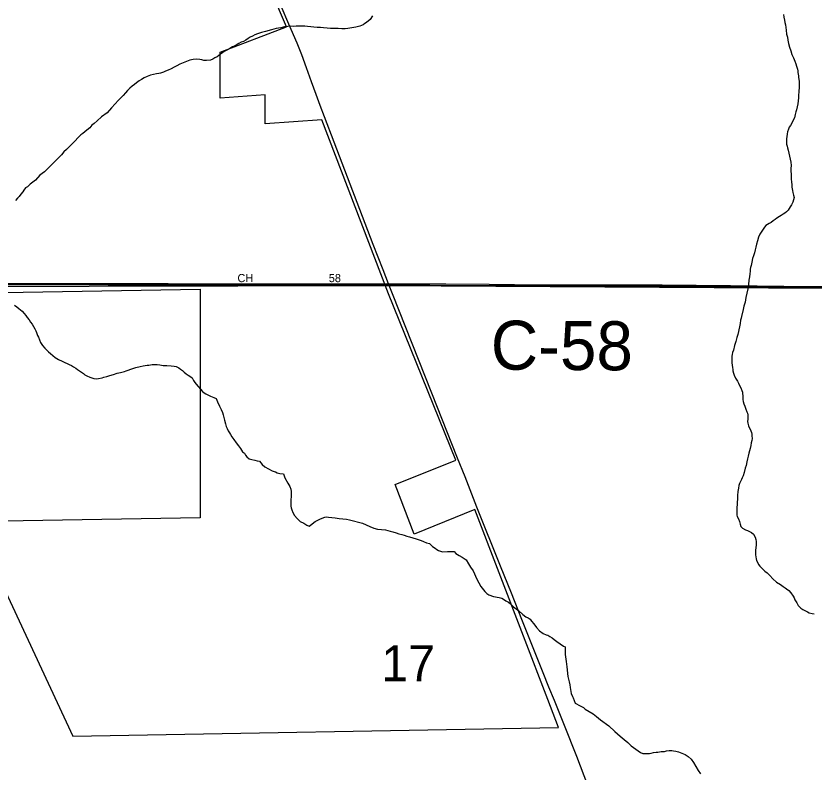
# Model space of a CAD drawing. Extents: x -17 to 88, y -5 to 22.
# Drawn here: x 3.752 to 4.677, y 17.592 to 18.469 of the extents above; entities that cross this region are included whole.
import ezdxf

# ---------------------------------------------------------------- set-up
doc = ezdxf.new("R2010")
doc.units = 0
for name, color, linetype in [('GM_X_City_Street', 7, 'Continuous'), ('GM_X_City_Street_Text', 7, 'Continuous'), ('GM_X_Corporation', 7, 'Continuous'), ('GM_X_County_Road', 7, 'Continuous'), ('GM_X_County_Road_Text', 7, 'Continuous'), ('GM_X_Minor_River', 7, 'Continuous'), ('GM_X_Section', 7, 'Continuous'), ('GM_X_Section_Text', 7, 'Continuous'), ('GM_X_Township', 7, 'Continuous')]:
    doc.layers.add(name, color=color, linetype=linetype)

msp = doc.modelspace()

# ---------------------------------------------------------------- linework, layer by layer
at = {"layer": 'GM_X_City_Street'}
msp.add_lwpolyline([(3.99092, 18.15844), (4.05569, 18.15826), (4.09422, 18.15814), (4.1551, 18.15821), (4.18362, 18.15825)], dxfattribs=at)
at = {"layer": 'GM_X_Corporation'}
msp.add_lwpolyline([(3.49838, 18.47232), (3.50032, 18.46598), (3.59822, 18.14576), (3.73721, 18.14819), (3.9654, 18.15217), (3.9654, 17.88702), (3.73721, 17.88304), (3.73721, 17.80634), (3.81765, 17.63383), (4.3806, 17.64365), (4.36804, 17.67637), (4.28354, 17.8965), (4.2133, 17.86812), (4.19124, 17.92558), (4.26148, 17.95396), (4.18358, 18.14677), (4.10614, 18.34852), (4.04077, 18.34395), (4.04077, 18.37728), (3.98843, 18.37362), (3.98843, 18.42684), (4.06517, 18.4563), (3.98399, 18.64755)], dxfattribs=at)
at = {"layer": 'GM_X_County_Road'}
for points in [[(4.06821, 18.4593), (4.05905, 18.48034), (4.04699, 18.5083), (4.0216, 18.56701), (4.00774, 18.60027), (3.9782, 18.67147), (3.96468, 18.70486), (3.95901, 18.71801), (3.95444, 18.7276), (3.95133, 18.73306), (3.94852, 18.73724), (3.94504, 18.74172), (3.94079, 18.74635), (3.93488, 18.75194), (3.92276, 18.76238)], [(4.10942, 18.35208), (4.10444, 18.36522), (4.09973, 18.37766), (4.09438, 18.39239), (4.08851, 18.40857), (4.08293, 18.42392), (4.07759, 18.43723), (4.06821, 18.4593)], [(4.18362, 18.15825), (4.17721, 18.17447), (4.16588, 18.20406), (4.12041, 18.32241), (4.10942, 18.35208)], [(3.59258, 18.15699), (3.59802, 18.15754), (3.60126, 18.1579), (3.60401, 18.15821), (3.60701, 18.15849), (3.61077, 18.1586), (3.65731, 18.15893), (3.68155, 18.15879), (3.69584, 18.15883), (3.71822, 18.15882), (3.74122, 18.1589), (3.82014, 18.15869), (3.86113, 18.15872), (3.909, 18.15858), (3.92826, 18.15851), (3.99092, 18.15844)], [(4.18362, 18.15825), (4.25001, 18.15841), (4.30029, 18.15788), (4.35872, 18.15724), (4.40659, 18.15707), (4.44511, 18.15703), (4.50048, 18.15708), (4.57968, 18.15636), (4.6414, 18.15574), (4.7084, 18.15531), (4.77224, 18.15491), (4.86303, 18.15388), (4.91889, 18.15329), (4.98138, 18.1518), (4.99507, 18.15157), (5.00005, 18.15168), (5.00329, 18.15186), (5.00624, 18.15209), (5.00931, 18.15257)], [(4.26356, 17.95598), (4.23353, 18.03166), (4.18817, 18.14672), (4.18362, 18.15825)], [(4.28604, 17.89935), (4.27231, 17.93461), (4.26356, 17.95598)], [(4.38743, 17.64619), (4.37578, 17.67507), (4.36936, 17.69056), (4.36282, 17.70734), (4.33812, 17.76899), (4.32598, 17.79958), (4.31347, 17.83072), (4.28604, 17.89935)], [(4.58217, 17.15264), (4.5624, 17.20125), (4.54521, 17.24457), (4.52486, 17.29667), (4.50254, 17.35334), (4.48523, 17.39664), (4.46504, 17.44678), (4.45566, 17.47112), (4.44651, 17.4945), (4.43032, 17.5366), (4.41884, 17.56546), (4.40173, 17.61014), (4.38743, 17.64619)]]:
    msp.add_lwpolyline(points, dxfattribs=at)
at = {"layer": 'GM_X_Minor_River'}
for points in [[(4.16515, 18.46903), (4.16208, 18.46488), (4.15788, 18.46112), (4.15597, 18.45999), (4.15406, 18.45849), (4.15025, 18.457), (4.14569, 18.4559), (4.13657, 18.45445), (4.13315, 18.4541), (4.12935, 18.45413), (4.12517, 18.45416), (4.121, 18.45419), (4.11644, 18.45422), (4.11227, 18.45463), (4.1081, 18.45505), (4.10468, 18.45545), (4.10088, 18.45548), (4.09709, 18.45589), (4.09367, 18.45629)], [(4.64129, 18.47071), (4.64165, 18.46729), (4.64238, 18.46387), (4.64274, 18.46121), (4.64349, 18.45855), (4.64384, 18.45552), (4.6442, 18.45248), (4.64455, 18.44792), (4.64566, 18.44412), (4.64639, 18.4407), (4.64713, 18.4369), (4.64823, 18.43271), (4.64972, 18.42853), (4.65083, 18.42435), (4.6527, 18.42016), (4.65419, 18.41635), (4.65531, 18.41331), (4.65643, 18.41065), (4.65754, 18.40722), (4.65791, 18.40532), (4.65789, 18.40342), (4.65826, 18.40152), (4.65863, 18.39925), (4.65861, 18.39735), (4.65898, 18.39545), (4.65934, 18.39279), (4.65932, 18.39013), (4.6593, 18.38748), (4.65887, 18.38027), (4.65847, 18.37762), (4.65844, 18.37382), (4.65804, 18.37042), (4.65763, 18.367), (4.65685, 18.36359), (4.65644, 18.36018), (4.65567, 18.35753), (4.65489, 18.3545), (4.6541, 18.35071), (4.65256, 18.34807), (4.65102, 18.34467), (4.64948, 18.34202), (4.64794, 18.33976), (4.64717, 18.33749), (4.64601, 18.33446), (4.64561, 18.33219), (4.64521, 18.32877), (4.64481, 18.32688), (4.6448, 18.32498), (4.64478, 18.32309), (4.64476, 18.32005), (4.64551, 18.31777), (4.64587, 18.31587), (4.64661, 18.3132), (4.64735, 18.30979), (4.64808, 18.30637), (4.64882, 18.30295), (4.64955, 18.29915), (4.6499, 18.29535), (4.64988, 18.29193), (4.64985, 18.28852), (4.65021, 18.28586), (4.65019, 18.28282), (4.65017, 18.27979), (4.65052, 18.27637), (4.65088, 18.27295), (4.65086, 18.2703), (4.65123, 18.2684), (4.65159, 18.2665), (4.65196, 18.26422)], [(4.09367, 18.45629), (4.0895, 18.45671), (4.08647, 18.45711), (4.08343, 18.45713), (4.08001, 18.45716), (4.0766, 18.45718), (4.07317, 18.45683), (4.07014, 18.45685), (4.06672, 18.4565), (4.06292, 18.45615), (4.05874, 18.45504), (4.05341, 18.45432), (4.04809, 18.45285), (4.04086, 18.45101), (4.03629, 18.44952), (4.03173, 18.44804), (4.02868, 18.44692), (4.02601, 18.44543), (4.02335, 18.44431), (4.02106, 18.44281), (4.01839, 18.44093), (4.01534, 18.43944), (4.01267, 18.43832), (4.01, 18.43682), (4.00695, 18.43495), (4.00467, 18.43383), (4.00276, 18.43308), (3.99971, 18.43121), (3.99704, 18.42971), (3.99399, 18.42822), (3.9917, 18.42634), (3.98903, 18.42446), (3.98674, 18.42296), (3.98483, 18.42146), (3.98217, 18.42034), (3.97988, 18.41884), (3.97721, 18.41772), (3.97265, 18.41738), (3.96962, 18.4174), (3.96734, 18.41817), (3.96507, 18.41857), (3.96051, 18.41861), (3.95709, 18.41825), (3.95329, 18.41752), (3.94948, 18.41603), (3.94567, 18.41455), (3.94187, 18.41306), (3.93844, 18.41119), (3.935, 18.40931), (3.93157, 18.40744), (3.92815, 18.40595), (3.9251, 18.40484), (3.92282, 18.40372), (3.91939, 18.4026), (3.91749, 18.40224), (3.91483, 18.40188), (3.91103, 18.40115), (3.9076, 18.40004), (3.90379, 18.39855), (3.90037, 18.39706), (3.89732, 18.39518), (3.89464, 18.39369), (3.89159, 18.39143), (3.8893, 18.38955), (3.88663, 18.3873), (3.88395, 18.38504), (3.88127, 18.3824), (3.8786, 18.37977), (3.87592, 18.37675), (3.87286, 18.37374), (3.87018, 18.37073), (3.86674, 18.36696), (3.86253, 18.36244), (3.85755, 18.3564), (3.85106, 18.3519), (3.84609, 18.34738), (3.84227, 18.344), (3.8396, 18.34212), (3.8373, 18.33911), (3.83386, 18.33648), (3.83157, 18.33459), (3.82928, 18.33272), (3.82699, 18.33084), (3.81704, 18.32067), (3.8136, 18.31728), (3.81054, 18.31389), (3.80748, 18.31126), (3.8048, 18.30786), (3.80136, 18.30485), (3.79792, 18.30146), (3.79409, 18.29732), (3.78989, 18.29318), (3.78491, 18.28828), (3.77957, 18.28415), (3.77459, 18.27849), (3.76848, 18.27399), (3.76504, 18.2706), (3.76276, 18.26948), (3.76084, 18.26684), (3.75969, 18.26495), (3.75739, 18.26231)], [(4.65196, 18.26422), (4.65269, 18.26118), (4.65343, 18.25852), (4.65187, 18.25284), (4.65033, 18.24981), (4.6488, 18.24755), (4.64649, 18.24377), (4.64458, 18.24189), (4.64267, 18.24038), (4.64076, 18.23888), (4.63847, 18.23738), (4.63657, 18.23626), (4.63351, 18.23438), (4.6316, 18.23288), (4.62932, 18.23138), (4.62703, 18.2295), (4.62474, 18.22838), (4.62283, 18.22688), (4.62092, 18.22575), (4.61901, 18.22387), (4.61671, 18.22047), (4.61517, 18.21821), (4.61364, 18.21594), (4.61209, 18.21254), (4.61092, 18.208), (4.60975, 18.20421), (4.60897, 18.2008), (4.60819, 18.19777), (4.60741, 18.19436), (4.60662, 18.19058), (4.60546, 18.18755), (4.60467, 18.18338), (4.60388, 18.17959), (4.60311, 18.17732), (4.60271, 18.17543), (4.60269, 18.17277), (4.60229, 18.16974), (4.60189, 18.16633), (4.6011, 18.16254), (4.60069, 18.15761), (4.59989, 18.1523), (4.59872, 18.14738), (4.59754, 18.14245), (4.59674, 18.13715), (4.59519, 18.13223), (4.5944, 18.12844), (4.59245, 18.12049), (4.59205, 18.11859), (4.59128, 18.11594), (4.59087, 18.11215), (4.59008, 18.10836), (4.58812, 18.09965), (4.58695, 18.09587), (4.58578, 18.09132), (4.58461, 18.08678), (4.58343, 18.08148), (4.58227, 18.07845), (4.58188, 18.07617), (4.58148, 18.07428), (4.58146, 18.07124), (4.58144, 18.06897), (4.58143, 18.06669), (4.58179, 18.06403), (4.58215, 18.06138), (4.58251, 18.0591), (4.5825, 18.0572), (4.58324, 18.05454), (4.58398, 18.05225), (4.58548, 18.04883), (4.58773, 18.0454), (4.58923, 18.04311), (4.59035, 18.04044), (4.59185, 18.03778), (4.59297, 18.03473), (4.59371, 18.03283), (4.5937, 18.03093), (4.59406, 18.02827), (4.59403, 18.0241), (4.59439, 18.02182), (4.59513, 18.01916), (4.59625, 18.01649), (4.59775, 18.01307), (4.59886, 18.01002), (4.59961, 18.00812), (4.59998, 18.00622), (4.59996, 18.00394), (4.59994, 18.00129), (4.59954, 17.99863), (4.59991, 17.99674), (4.60065, 17.9937), (4.60326, 17.98798), (4.604, 17.9857), (4.60437, 17.9838), (4.60436, 17.9819), (4.60471, 17.97887), (4.60432, 17.97659), (4.60392, 17.97394), (4.60352, 17.97091), (4.60274, 17.9675), (4.60195, 17.96447), (4.60118, 17.96182)], [(3.75739, 18.26231), (3.75547, 18.25967), (3.75356, 18.25741), (3.75126, 18.25477)], [(3.75, 18.13336), (3.75303, 18.13144), (3.75529, 18.12952), (3.75718, 18.12799), (3.75907, 18.12646), (3.76133, 18.12379), (3.76321, 18.1215), (3.76471, 18.11921), (3.76697, 18.11654), (3.76885, 18.11387), (3.77073, 18.11157), (3.77223, 18.10891), (3.77373, 18.10624), (3.77485, 18.10357), (3.7756, 18.10167), (3.77671, 18.09825), (3.77784, 18.09634), (3.77895, 18.0933), (3.78045, 18.09025), (3.7827, 18.08682), (3.78534, 18.08376), (3.7876, 18.08147), (3.78949, 18.07956), (3.79175, 18.07764), (3.79439, 18.07535), (3.79741, 18.07267), (3.80119, 18.07036), (3.80535, 18.06843), (3.80838, 18.0669), (3.81103, 18.06574), (3.81368, 18.06458), (3.81633, 18.06342), (3.8186, 18.06188), (3.82124, 18.06035), (3.82313, 18.05881), (3.8254, 18.05728), (3.82766, 18.05574), (3.82993, 18.05421), (3.83182, 18.05268)], [(3.83182, 18.05268), (3.83409, 18.05152), (3.83749, 18.04998), (3.84204, 18.04843), (3.84545, 18.04802), (3.84735, 18.04839), (3.85154, 18.04911), (3.85382, 18.04985), (3.85724, 18.05097), (3.86067, 18.05208), (3.86485, 18.05318), (3.86904, 18.05467), (3.87285, 18.0554), (3.87589, 18.05613), (3.87779, 18.0565), (3.87969, 18.05724), (3.88197, 18.05799), (3.88502, 18.05948), (3.89073, 18.06134), (3.89567, 18.06244), (3.8991, 18.06317), (3.90138, 18.06353), (3.90404, 18.06389), (3.90594, 18.06388), (3.90784, 18.06424), (3.90974, 18.0646), (3.91278, 18.06458), (3.91544, 18.06456), (3.91847, 18.06416), (3.92226, 18.06375), (3.92682, 18.06372), (3.93175, 18.0633), (3.93517, 18.06289), (3.93744, 18.0625), (3.94047, 18.06096), (3.94236, 18.05942), (3.94462, 18.05789), (3.94689, 18.05597), (3.94915, 18.05406), (3.95142, 18.05253), (3.95331, 18.05137), (3.95595, 18.04908), (3.95745, 18.04603), (3.95895, 18.04374), (3.96046, 18.04183), (3.96799, 18.03343), (3.96988, 18.0319), (3.97177, 18.03074), (3.97404, 18.02959), (3.97744, 18.02804), (3.97934, 18.02727), (3.98123, 18.0265), (3.98388, 18.02534), (3.98537, 18.02153), (3.98761, 18.01658), (3.98948, 18.01239), (3.99097, 18.00897), (3.99209, 18.00631), (3.99283, 18.00326), (3.99357, 18.00022), (3.99468, 17.99604), (3.99541, 17.993), (3.99653, 17.99033), (3.99765, 17.98767), (3.99916, 17.98538), (4.00028, 17.98348), (4.00216, 17.98081), (4.00442, 17.97775), (4.00705, 17.97394), (4.00968, 17.9705), (4.01194, 17.96745), (4.01419, 17.96364), (4.01683, 17.96172), (4.01795, 17.95944), (4.01946, 17.95753), (4.0221, 17.95523), (4.02513, 17.95445), (4.02854, 17.95367), (4.0312, 17.95288), (4.03385, 17.95249), (4.03724, 17.94867), (4.04026, 17.94599), (4.04858, 17.94137), (4.05085, 17.94059), (4.05275, 17.9402), (4.05464, 17.93905), (4.05767, 17.93827), (4.06184, 17.93785), (4.06333, 17.93329), (4.0667, 17.92719), (4.06933, 17.92338), (4.07045, 17.92034), (4.07081, 17.9173), (4.07079, 17.91464), (4.07076, 17.91123), (4.07036, 17.90819), (4.07033, 17.90402), (4.07031, 17.90061), (4.07067, 17.89833), (4.07141, 17.89604), (4.07253, 17.893)], [(4.60118, 17.96182), (4.60039, 17.95841), (4.59961, 17.95538), (4.59883, 17.95197), (4.59804, 17.9478), (4.59687, 17.9444), (4.5957, 17.93947), (4.59453, 17.93569), (4.59338, 17.93342), (4.5926, 17.93153), (4.59145, 17.92888), (4.59029, 17.92661), (4.58952, 17.92434), (4.58911, 17.92131), (4.58833, 17.91752), (4.58791, 17.91297), (4.58788, 17.9088), (4.58747, 17.90463), (4.58746, 17.90197), (4.58706, 17.89932), (4.58703, 17.8959), (4.58701, 17.89249), (4.58699, 17.89021), (4.58736, 17.88831), (4.58924, 17.88564), (4.59035, 17.8826), (4.59109, 17.87956), (4.59183, 17.8769), (4.59371, 17.87499), (4.59712, 17.87306), (4.59939, 17.87228), (4.60431, 17.86997), (4.60658, 17.86806), (4.60845, 17.86463), (4.60919, 17.86196), (4.60955, 17.85931), (4.60952, 17.85551), (4.60912, 17.8521), (4.60872, 17.84945), (4.6087, 17.84641), (4.60868, 17.84414), (4.60904, 17.84186), (4.60941, 17.8392), (4.60977, 17.8373), (4.61127, 17.83463), (4.6124, 17.83273), (4.6139, 17.83081), (4.61692, 17.82776), (4.61956, 17.82508), (4.6222, 17.82317), (4.62521, 17.82011), (4.62898, 17.81628), (4.63313, 17.81246), (4.63767, 17.80977), (4.64069, 17.80747), (4.64296, 17.80593), (4.64485, 17.80478), (4.64749, 17.80248), (4.64975, 17.79981), (4.65238, 17.79599), (4.6535, 17.79409), (4.65425, 17.79181), (4.6565, 17.78837), (4.65838, 17.78532), (4.66139, 17.78227), (4.66366, 17.78073), (4.66593, 17.77957), (4.66896, 17.77803), (4.67085, 17.77688), (4.67426, 17.7761), (4.67691, 17.7757)], [(4.07253, 17.893), (4.07478, 17.88957), (4.0778, 17.88613), (4.08119, 17.88269), (4.08535, 17.88076), (4.08875, 17.87846), (4.0914, 17.8773), (4.09331, 17.87842), (4.09866, 17.88256), (4.10475, 17.88592), (4.1097, 17.88778), (4.1116, 17.88815), (4.11388, 17.88775), (4.11767, 17.88734), (4.12185, 17.88693), (4.1264, 17.88614), (4.13057, 17.88573), (4.13474, 17.88532), (4.13816, 17.88453), (4.15332, 17.88062), (4.15748, 17.87869), (4.16202, 17.87676), (4.16657, 17.87483), (4.17073, 17.87366), (4.17528, 17.87324), (4.17984, 17.87283), (4.18287, 17.87243), (4.18553, 17.87165), (4.18856, 17.87087), (4.19235, 17.8697), (4.19537, 17.86854), (4.19879, 17.86775), (4.20182, 17.86697), (4.20485, 17.86581), (4.20788, 17.86503), (4.21167, 17.86386), (4.21546, 17.86269), (4.21886, 17.86153), (4.22152, 17.86075), (4.22417, 17.85959), (4.22757, 17.85805), (4.23099, 17.85726), (4.23438, 17.85382), (4.2374, 17.8519), (4.23967, 17.85037), (4.24156, 17.84921), (4.2461, 17.84766), (4.2518, 17.848), (4.25712, 17.84796), (4.25977, 17.84794), (4.26166, 17.84565), (4.26544, 17.84334), (4.26884, 17.84142), (4.27337, 17.83835), (4.27638, 17.83377), (4.27863, 17.82958), (4.28163, 17.82538), (4.28574, 17.81587), (4.29062, 17.80748), (4.29513, 17.80138), (4.29739, 17.79908), (4.29966, 17.79755), (4.30534, 17.79561), (4.31179, 17.79442), (4.31482, 17.79364), (4.31671, 17.79249), (4.31935, 17.79057), (4.32238, 17.78903), (4.32502, 17.78711), (4.32842, 17.78367), (4.33446, 17.77907), (4.33898, 17.77486), (4.34276, 17.77218), (4.34541, 17.77102), (4.34768, 17.76948), (4.34918, 17.76719), (4.35182, 17.76414), (4.35482, 17.75994), (4.35859, 17.75574), (4.36274, 17.75267), (4.36615, 17.75113), (4.36805, 17.75074), (4.37031, 17.7492), (4.37296, 17.74766), (4.3756, 17.74574), (4.37862, 17.74344), (4.3824, 17.74076), (4.38618, 17.73808), (4.38807, 17.7373), (4.38839, 17.72857), (4.38947, 17.72022), (4.39018, 17.71414), (4.39124, 17.70313), (4.39272, 17.69667), (4.39345, 17.69325), (4.39419, 17.6902), (4.39528, 17.68337), (4.39677, 17.67994), (4.39752, 17.67804), (4.39975, 17.67195), (4.40542, 17.66887)], [(4.40542, 17.66887), (4.40959, 17.66694), (4.41147, 17.66503), (4.41601, 17.66234), (4.42055, 17.65965), (4.4247, 17.65658), (4.42923, 17.65275), (4.43867, 17.64585), (4.44584, 17.63934), (4.45187, 17.63361), (4.4564, 17.62978), (4.46093, 17.62633), (4.4647, 17.62251), (4.47566, 17.61483), (4.47831, 17.61368), (4.48135, 17.61365), (4.48362, 17.61364), (4.4859, 17.61362), (4.4878, 17.61398), (4.49046, 17.61472), (4.4935, 17.61508), (4.49578, 17.61506), (4.49768, 17.61543), (4.49959, 17.61579), (4.50339, 17.61614), (4.50567, 17.61688), (4.50871, 17.61724), (4.51174, 17.61722), (4.51364, 17.61682), (4.5163, 17.61642), (4.51971, 17.61564), (4.52349, 17.61409), (4.52728, 17.61254), (4.53068, 17.61024), (4.53408, 17.60718), (4.53709, 17.60336), (4.53971, 17.59841), (4.54233, 17.59384), (4.54496, 17.59002)]]:
    msp.add_lwpolyline(points, dxfattribs=at)
at = {"layer": 'GM_X_Section'}
for points in [[(3.73257, 19.16304), (4.72971, 19.15674), (4.72866, 18.15461), (3.73415, 18.15786)], [(3.73415, 18.15786), (4.72866, 18.15461), (4.72799, 17.15249), (3.73424, 17.15574)]]:
    msp.add_lwpolyline(points, close=True, dxfattribs=at)
at = {"layer": 'GM_X_Township'}
for points in [[(2.68822, 20.9), (2.68323, 20.17621), (2.68252, 19.99244), (2.68206, 19.87448), (2.68103, 19.61133), (2.67924, 19.15351), (2.67029, 18.1495), (3.1789, 18.15325), (3.49159, 18.15481), (4.18133, 18.15639), (5.00335, 18.15133), (5.04642, 18.15132), (5.71493, 18.14695)], [(5.71493, 18.14695), (5.04642, 18.15132), (5.00335, 18.15133), (4.18133, 18.15639), (3.49159, 18.15481), (3.1789, 18.15325), (2.67029, 18.1495), (2.66111, 17.53897), (2.63299, 16.1443), (2.61254, 14.64771), (2.60542, 14.15466), (2.60501, 14.1)]]:
    msp.add_lwpolyline(points, dxfattribs=at)

# ---------------------------------------------------------------- texts
at = {"layer": 'GM_X_City_Street_Text'}
for s, p in [('CH', (4.00849, 18.1602)), ('58', (4.11432, 18.1602))]:
    msp.add_text(s, height=0.00947, rotation=0.00001, dxfattribs=at).set_placement(p)
at = {"layer": 'GM_X_County_Road_Text'}
msp.add_text('C-58', height=0.056818, rotation=359.65539, dxfattribs=at).set_placement((4.30189, 18.05887))
at = {"layer": 'GM_X_Section_Text'}
msp.add_text('17', height=0.041856, rotation=0.00001, dxfattribs=at).set_placement((4.17516, 17.69733))

doc.saveas('drawing.dxf')
